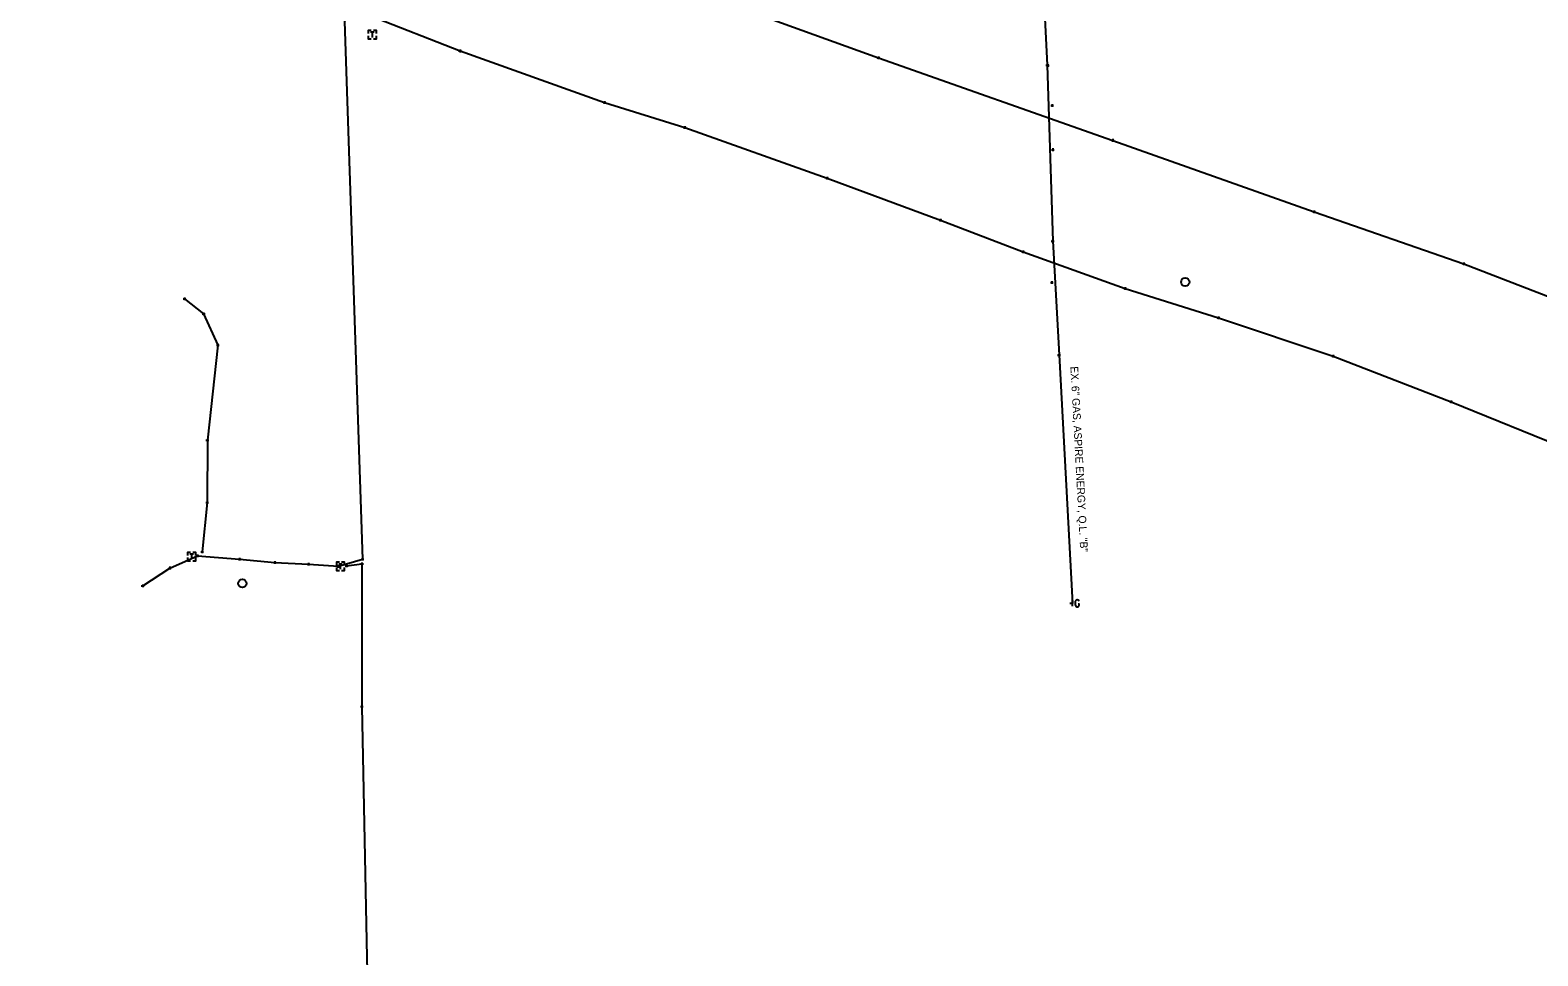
# Model space of a CAD drawing. Extents: x 2046588 to 2048646, y 455919 to 457871.
# Drawn here: x 2047549 to 2048096, y 456615 to 456951 of the extents above; entities that cross this region are included whole.
import ezdxf

# ---------------------------------------------------------------- set-up
doc = ezdxf.new("R2010")
doc.units = 0
for name, color, linetype in [('CM_Corridor_Top_Mesh', 7, 'Continuous'), ('MD_P_Surface_Curb', 7, 'Continuous'), ('UT_P_Gas', 7, 'Continuous'), ('UT_X_FO', 7, 'Continuous'), ('UT_X_Gas', 7, 'Continuous'), ('UT_X_Overhead_Combined', 7, 'Continuous'), ('UT_X_Overhead_Telecom', 7, 'Continuous'), ('UT_X_Telecom_Text', 7, 'Continuous')]:
    doc.layers.add(name, color=color, linetype=linetype)

msp = doc.modelspace()

# ---------------------------------------------------------------- linework, layer by layer
at = {"layer": 'CM_Corridor_Top_Mesh'}
for points in [[(2047665.85, 457013.41), (2047668, 456994.57), (2047668.07, 456981.81), (2047669.2, 456967.36), (2047663.52, 456954.27), (2047669.97, 456759.3)], [(2047667.24, 457010.56), (2047697.33, 456993.62), (2047786.8, 456966.6), (2047857.15, 456941.14), (2047942.17, 456911.18), (2048015.15, 456885.28), (2048069.44, 456866.41), (2048172.16, 456826.67), (2048228.9, 456807.13), (2048277.95, 456789.73), (2048347.98, 456763.63), (2048445.37, 456729.99), (2048495.85, 456709.95), (2048575.59, 456682.31), (2048645.25, 456657.54)], [(2047605.42, 456853.67), (2047612.36, 456848.22), (2047617.49, 456836.84), (2047613.71, 456802.4), (2047613.66, 456779.8), (2047611.84, 456761.96)], [(2047590.26, 456749.58), (2047600.12, 456756.04), (2047610.13, 456760.45), (2047625.43, 456759.23), (2047638.22, 456758.03), (2047650.4, 456757.48), (2047661.32, 456756.67), (2047669.97, 456759.3)], [(2047664.23, 456756.81), (2047669.8, 456757.54), (2047669.74, 456705.78), (2047671.58, 456614.77), (2047674.06, 456510.32), (2047676.92, 456406.31), (2047679.08, 456361.81), (2047678.89, 456329.69), (2047678.68, 456325.08)]]:
    msp.add_lwpolyline(points, dxfattribs=at)
at = {"layer": 'UT_P_Gas'}
for p, q in [((2047672.92, 456950.52), (2047674.22, 456950.52)), ((2047673.57, 456948.52), (2047673.57, 456950.52)), ((2047673.57, 456949.52), (2047673.57, 456949.52)), ((2047607.4, 456761.21), (2047608.7, 456761.21)), ((2047608.05, 456759.21), (2047608.05, 456761.21)), ((2047608.05, 456760.21), (2047608.05, 456760.21)), ((2047661.36, 456757.62), (2047662.66, 456757.62)), ((2047662.01, 456755.62), (2047662.01, 456757.62)), ((2047662.01, 456756.62), (2047662.01, 456756.62))]:
    msp.add_line(p, q, dxfattribs=at)
for points in [[(2047673.17, 456951.02), (2047672.07, 456951.02), (2047672.07, 456949.92)], [(2047672.07, 456949.12), (2047672.07, 456948.02), (2047673.17, 456948.02)], [(2047675.07, 456949.92), (2047675.07, 456951.02), (2047673.97, 456951.02)], [(2047673.97, 456948.02), (2047675.07, 456948.02), (2047675.07, 456949.12)], [(2047607.65, 456761.71), (2047606.55, 456761.71), (2047606.55, 456760.61)], [(2047609.55, 456760.61), (2047609.55, 456761.71), (2047608.45, 456761.71)], [(2047606.55, 456759.81), (2047606.55, 456758.71), (2047607.65, 456758.71)], [(2047608.45, 456758.71), (2047609.55, 456758.71), (2047609.55, 456759.81)], [(2047661.61, 456758.12), (2047660.51, 456758.12), (2047660.51, 456757.02)], [(2047660.51, 456756.22), (2047660.51, 456755.12), (2047661.61, 456755.12)], [(2047663.51, 456757.02), (2047663.51, 456758.12), (2047662.41, 456758.12)], [(2047662.41, 456755.12), (2047663.51, 456755.12), (2047663.51, 456756.22)]]:
    msp.add_lwpolyline(points, dxfattribs=at)
at = {"layer": 'UT_X_FO'}
for p, q in [((2047927.48, 456742.21), (2047927.48, 456744.21)), ((2047927.48, 456743.21), (2047926.53, 456743.21))]:
    msp.add_line(p, q, dxfattribs=at)
msp.add_lwpolyline([(2047929.96, 456743.97), (2047929.94, 456744.06), (2047929.88, 456744.16), (2047929.78, 456744.26), (2047929.64, 456744.38), (2047929.54, 456744.42), (2047929.46, 456744.44), (2047929.35, 456744.46), (2047929.11, 456744.46), (2047929.01, 456744.44), (2047928.95, 456744.42), (2047928.87, 456744.38), (2047928.72, 456744.26), (2047928.62, 456744.12), (2047928.56, 456743.97), (2047928.52, 456743.75), (2047928.48, 456743.43), (2047928.48, 456743.02), (2047928.5, 456742.69), (2047928.58, 456742.43), (2047928.7, 456742.19), (2047928.79, 456742.12), (2047928.91, 456742.04), (2047929.13, 456741.96), (2047929.35, 456741.96), (2047929.56, 456742), (2047929.64, 456742.04), (2047929.72, 456742.08), (2047929.8, 456742.15), (2047929.88, 456742.27), (2047929.96, 456742.45), (2047929.96, 456742.94), (2047929.54, 456742.94)], dxfattribs=at)
at = {"layer": 'UT_X_Gas'}
for p, q in [((2047704.87, 456943.59), (2047705.87, 456943.59)), ((2047705.37, 456944.09), (2047705.37, 456943.09)), ((2047705.37, 456943.59), (2047705.37, 456943.59)), ((2047856.65, 456941.14), (2047857.65, 456941.14)), ((2047857.15, 456941.64), (2047857.15, 456940.64)), ((2047857.15, 456941.14), (2047857.15, 456941.14)), ((2047917.83, 456938.4), (2047918.83, 456938.4)), ((2047918.11, 456938.35), (2047919.11, 456938.35)), ((2047918.33, 456938.9), (2047918.33, 456937.9)), ((2047918.33, 456938.4), (2047918.33, 456938.4)), ((2047918.61, 456938.85), (2047918.61, 456937.85)), ((2047918.61, 456938.35), (2047918.61, 456938.35)), ((2047757.27, 456924.93), (2047758.27, 456924.93)), ((2047757.77, 456925.43), (2047757.77, 456924.43)), ((2047757.77, 456924.93), (2047757.77, 456924.93)), ((2047920.17, 456924.33), (2047920.17, 456923.33)), ((2047919.67, 456923.83), (2047920.67, 456923.83)), ((2047920.17, 456923.83), (2047920.17, 456923.83)), ((2047786.36, 456915.85), (2047787.36, 456915.85)), ((2047786.86, 456916.35), (2047786.86, 456915.35)), ((2047786.86, 456915.85), (2047786.86, 456915.85)), ((2047920.41, 456908.29), (2047920.41, 456907.29)), ((2047941.67, 456911.18), (2047942.67, 456911.18)), ((2047942.17, 456911.68), (2047942.17, 456910.68)), ((2047942.17, 456911.18), (2047942.17, 456911.18)), ((2047919.91, 456907.79), (2047920.91, 456907.79)), ((2047920.41, 456907.79), (2047920.41, 456907.79)), ((2047838.05, 456897.47), (2047839.05, 456897.47)), ((2047838.55, 456897.97), (2047838.55, 456896.97)), ((2047838.55, 456897.47), (2047838.55, 456897.47)), ((2047879.16, 456882.22), (2047880.16, 456882.22)), ((2047879.66, 456882.72), (2047879.66, 456881.72)), ((2047879.66, 456882.22), (2047879.66, 456882.22)), ((2048014.65, 456885.28), (2048015.65, 456885.28)), ((2048015.15, 456885.78), (2048015.15, 456884.78)), ((2048015.15, 456885.28), (2048015.15, 456885.28)), ((2047920.31, 456875.11), (2047920.31, 456874.11)), ((2047920.4, 456875.15), (2047920.4, 456874.15)), ((2047909.15, 456870.7), (2047910.15, 456870.7)), ((2047909.65, 456871.2), (2047909.65, 456870.2)), ((2047909.65, 456870.7), (2047909.65, 456870.7)), ((2047919.81, 456874.61), (2047920.81, 456874.61)), ((2047919.9, 456874.65), (2047920.9, 456874.65)), ((2047920.31, 456874.61), (2047920.31, 456874.61)), ((2047920.4, 456874.65), (2047920.4, 456874.65)), ((2048068.94, 456866.41), (2048069.94, 456866.41)), ((2048069.44, 456866.91), (2048069.44, 456865.91)), ((2048069.44, 456866.41), (2048069.44, 456866.41)), ((2047919.55, 456859.62), (2047920.55, 456859.62)), ((2047920.05, 456860.12), (2047920.05, 456859.12)), ((2047920.05, 456859.62), (2047920.05, 456859.62)), ((2047604.92, 456853.67), (2047605.92, 456853.67)), ((2047605.42, 456854.17), (2047605.42, 456853.17)), ((2047605.42, 456853.67), (2047605.42, 456853.67)), ((2047946.15, 456857.43), (2047947.15, 456857.43)), ((2047946.65, 456857.93), (2047946.65, 456856.93)), ((2047946.65, 456857.43), (2047946.65, 456857.43)), ((2047611.86, 456848.22), (2047612.86, 456848.22)), ((2047612.36, 456848.72), (2047612.36, 456847.72)), ((2047612.36, 456848.22), (2047612.36, 456848.22)), ((2047979.96, 456846.8), (2047980.96, 456846.8)), ((2047980.46, 456847.3), (2047980.46, 456846.3)), ((2047980.46, 456846.8), (2047980.46, 456846.8)), ((2047616.99, 456836.84), (2047617.99, 456836.84)), ((2047617.49, 456837.34), (2047617.49, 456836.34)), ((2047617.49, 456836.84), (2047617.49, 456836.84)), ((2047922.15, 456833.29), (2047923.15, 456833.29)), ((2047922.17, 456833.39), (2047923.17, 456833.39)), ((2047922.65, 456833.79), (2047922.65, 456832.79)), ((2047922.65, 456833.29), (2047922.65, 456833.29)), ((2047922.67, 456833.89), (2047922.67, 456832.89)), ((2047922.67, 456833.39), (2047922.67, 456833.39)), ((2048021.6, 456832.89), (2048022.6, 456832.89)), ((2048022.1, 456833.39), (2048022.1, 456832.39)), ((2048022.1, 456832.89), (2048022.1, 456832.89)), ((2048064.35, 456816.32), (2048065.35, 456816.32)), ((2048064.85, 456816.82), (2048064.85, 456815.82)), ((2048064.85, 456816.32), (2048064.85, 456816.32)), ((2047613.21, 456802.4), (2047614.21, 456802.4)), ((2047613.71, 456802.9), (2047613.71, 456801.9)), ((2047613.71, 456802.4), (2047613.71, 456802.4)), ((2047613.16, 456779.8), (2047614.16, 456779.8)), ((2047613.66, 456780.3), (2047613.66, 456779.3)), ((2047613.66, 456779.8), (2047613.66, 456779.8)), ((2047609.63, 456760.45), (2047610.63, 456760.45)), ((2047610.13, 456760.95), (2047610.13, 456759.95)), ((2047610.13, 456760.45), (2047610.13, 456760.45)), ((2047611.34, 456761.96), (2047612.34, 456761.96)), ((2047611.84, 456762.46), (2047611.84, 456761.46)), ((2047611.84, 456761.96), (2047611.84, 456761.96)), ((2047599.62, 456756.04), (2047600.62, 456756.04)), ((2047600.12, 456756.54), (2047600.12, 456755.54)), ((2047600.12, 456756.04), (2047600.12, 456756.04)), ((2047624.93, 456759.23), (2047625.93, 456759.23)), ((2047625.43, 456759.73), (2047625.43, 456758.73)), ((2047625.43, 456759.23), (2047625.43, 456759.23)), ((2047637.72, 456758.03), (2047638.72, 456758.03)), ((2047638.22, 456758.53), (2047638.22, 456757.53)), ((2047638.22, 456758.03), (2047638.22, 456758.03)), ((2047649.9, 456757.48), (2047650.9, 456757.48)), ((2047650.4, 456757.98), (2047650.4, 456756.98)), ((2047650.4, 456757.48), (2047650.4, 456757.48)), ((2047660.82, 456756.67), (2047661.82, 456756.67)), ((2047661.32, 456757.17), (2047661.32, 456756.17)), ((2047661.32, 456756.67), (2047661.32, 456756.67)), ((2047663.73, 456756.81), (2047664.73, 456756.81)), ((2047664.23, 456757.31), (2047664.23, 456756.31)), ((2047664.23, 456756.81), (2047664.23, 456756.81)), ((2047669.3, 456757.54), (2047670.3, 456757.54)), ((2047669.47, 456759.3), (2047670.47, 456759.3)), ((2047669.8, 456758.04), (2047669.8, 456757.04)), ((2047669.8, 456757.54), (2047669.8, 456757.54)), ((2047669.97, 456759.8), (2047669.97, 456758.8)), ((2047669.97, 456759.3), (2047669.97, 456759.3)), ((2047589.76, 456749.58), (2047590.76, 456749.58)), ((2047590.26, 456750.08), (2047590.26, 456749.08)), ((2047590.26, 456749.58), (2047590.26, 456749.58)), ((2047669.24, 456705.78), (2047670.24, 456705.78)), ((2047669.74, 456706.28), (2047669.74, 456705.28)), ((2047669.74, 456705.78), (2047669.74, 456705.78))]:
    msp.add_line(p, q, dxfattribs=at)
at = {"layer": 'UT_X_Overhead_Combined'}
msp.add_lwpolyline([(2047535.14, 457007.65), (2047572.61, 456989.81), (2047612.33, 456976.78), (2047633.35, 456969.75), (2047653.85, 456962.85), (2047672.62, 456956.44), (2047705.37, 456943.59), (2047757.77, 456924.93), (2047786.86, 456915.85), (2047838.55, 456897.47), (2047879.66, 456882.22), (2047909.65, 456870.7), (2047946.65, 456857.43), (2047980.46, 456846.8), (2048022.1, 456832.89), (2048064.85, 456816.32), (2048107.79, 456798.87)], dxfattribs=at)
at = {"layer": 'UT_X_Overhead_Telecom'}
for points in [[(2047916.51, 457112.29), (2047915.8, 457054.38), (2047916.89, 456995.27), (2047916.96, 456965.32), (2047918.33, 456938.4), (2047920.4, 456874.65), (2047922.67, 456833.39)], [(2047922.67, 456833.39), (2047927.48, 456743.21)]]:
    msp.add_lwpolyline(points, dxfattribs=at)
at = {"layer": 'UT_X_Telecom_Text'}
for centre in [(2047968.43, 456859.79), (2047626.41, 456750.46)]:
    msp.add_circle(centre, 1.5, dxfattribs=at)

# ---------------------------------------------------------------- texts
at = {"layer": 'MD_P_Surface_Curb'}
msp.add_text('EX. 6" GAS, ASPIRE ENERGY, Q.L. "B"', height=2.8, rotation=273.0501, dxfattribs=at).set_placement((2047926.77, 456829.12))

doc.saveas('drawing.dxf')
